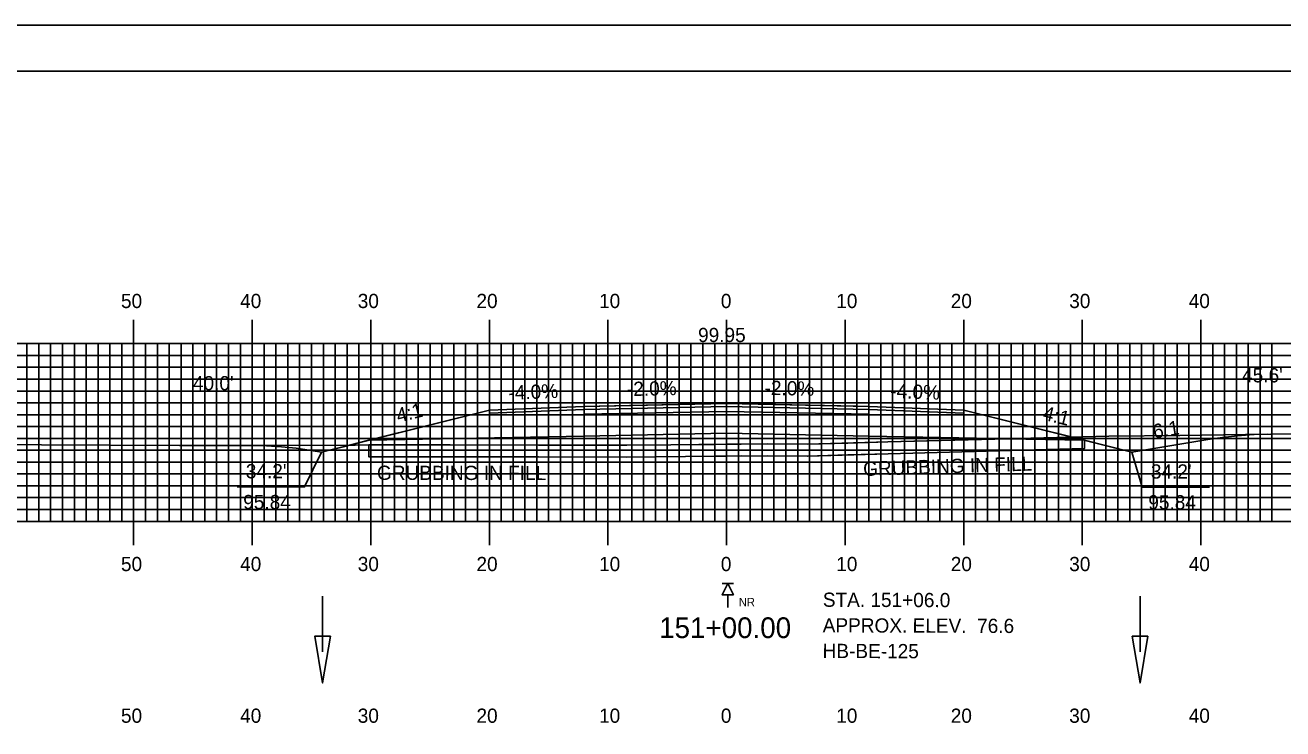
# Model space of a CAD drawing. Extents: x 1778319 to 1778662, y 442591 to 442811.
# Drawn here: x 1778425.2 to 1778531.2, y 442751.2 to 442810.5 of the extents above; entities that cross this region are included whole.
import ezdxf

# ---------------------------------------------------------------- set-up
doc = ezdxf.new("R2010")
doc.units = 0
for name, color, linetype in [('ANNOTATION', 7, 'Continuous'), ('BORDER', 7, 'Continuous'), ('BORING - NO REFUSAL', 7, 'Continuous'), ('D_Drainage_Ditch_Line', 7, 'Continuous'), ('D_Roadway_Centerline', 7, 'Continuous'), ('D_Roadway_Centerline_Text', 7, 'Continuous'), ('D_Roadway_Edge_Shoulder', 7, 'Continuous'), ('D_Roadway_Edge_TW', 7, 'Continuous'), ('D_Roadway_Pavement', 7, 'Continuous'), ('D_Roadway_SlopeLines', 7, 'Continuous'), ('D_Roadway_SubGrade', 7, 'Continuous'), ('D_Text_Standard', 7, 'Continuous'), ('GRUBBING IN FILL', 7, 'Continuous'), ('H_V ANNOTATION', 7, 'Continuous'), ('MAJOR', 7, 'Continuous'), ('MINOR', 7, 'Continuous'), ('PLOT BOUNDARY', 7, 'Continuous'), ('S_Roadway_Centerline', 7, 'Continuous')]:
    doc.layers.add(name, color=color, linetype=linetype)

msp = doc.modelspace()

# ---------------------------------------------------------------- linework, layer by layer
at = {"layer": 'ANNOTATION'}
for points in [[(1778443.02, 442771.57), (1778448.71, 442771.57), (1778450.13, 442774.51)], [(1778525.04, 442771.56), (1778519.35, 442771.56), (1778518.48, 442774.51)]]:
    msp.add_lwpolyline(points, dxfattribs=at)
at = {"layer": 'BORDER'}
msp.add_lwpolyline([(1778334.7, 442596.67), (1778654.7, 442596.67), (1778654.7, 442806.67), (1778334.7, 442806.67)], close=True, dxfattribs=at)
at = {"layer": 'BORING - NO REFUSAL'}
for p, q in [((1778484.88, 442763.43), (1778483.92, 442763.43)), ((1778484.4, 442762.47), (1778484.4, 442761.41))]:
    msp.add_line(p, q, dxfattribs=at)
msp.add_lwpolyline([(1778484.4, 442763.43), (1778484.88, 442762.47), (1778483.92, 442762.47)], close=True, dxfattribs=at)
at = {"layer": 'D_Drainage_Ditch_Line'}
for p, q in [((1778450.24, 442757.66), (1778450.24, 442762.36)), ((1778519.17, 442757.66), (1778519.17, 442762.36))]:
    msp.add_line(p, q, dxfattribs=at)
for points in [[(1778450.9, 442758.97), (1778449.58, 442758.97), (1778450.24, 442755.04)], [(1778519.82, 442758.97), (1778518.51, 442758.97), (1778519.17, 442755.04)]]:
    msp.add_lwpolyline(points, close=True, dxfattribs=at)
at = {"layer": 'D_Roadway_Centerline'}
msp.add_lwpolyline([(1778444.26, 442775.06), (1778445.51, 442775.04), (1778446.76, 442774.97), (1778448.01, 442774.84), (1778449.26, 442774.65), (1778449.96, 442774.54), (1778450.13, 442774.51), (1778451.86, 442774.94), (1778454.13, 442775.51), (1778464.3, 442778.05), (1778472.3, 442778.37), (1778476.13, 442778.45), (1778484.3, 442778.61), (1778495.33, 442778.39), (1778496.3, 442778.37), (1778504.3, 442778.05), (1778514.48, 442775.51), (1778518.48, 442774.51), (1778524.89, 442775.58), (1778526.14, 442775.76), (1778527.39, 442775.9), (1778528.4, 442775.97), (1778528.64, 442775.99), (1778528.81, 442775.99), (1778529.89, 442776.03)], dxfattribs=at)
at = {"layer": 'D_Roadway_Edge_Shoulder'}
for points in [[(1778472.3, 442778.37), (1778464.3, 442778.05), (1778464.3, 442777.8), (1778472.3, 442778.12)], [(1778496.3, 442778.37), (1778504.3, 442778.05), (1778504.3, 442777.8), (1778496.3, 442778.12)]]:
    msp.add_lwpolyline(points, close=True, dxfattribs=at)
at = {"layer": 'D_Roadway_Edge_TW'}
msp.add_lwpolyline([(1778472.3, 442778.12), (1778472.3, 442778.37), (1778484.3, 442778.61), (1778496.3, 442778.37), (1778496.3, 442778.12), (1778484.3, 442778.36)], close=True, dxfattribs=at)
at = {"layer": 'D_Roadway_Pavement'}
msp.add_lwpolyline([(1778472.3, 442777.71), (1778472.3, 442778.12), (1778484.3, 442778.36), (1778496.3, 442778.12), (1778496.3, 442777.71), (1778484.3, 442777.95)], close=True, dxfattribs=at)
at = {"layer": 'D_Roadway_SlopeLines'}
for points in [[(1778464.3, 442778.05), (1778450.13, 442774.51)], [(1778504.3, 442778.05), (1778518.48, 442774.51)], [(1778518.48, 442774.51), (1778524.89, 442775.58), (1778526.14, 442775.76), (1778527.39, 442775.9), (1778528.64, 442775.99), (1778529.89, 442776.03)], [(1778450.13, 442774.51), (1778449.26, 442774.65), (1778448.01, 442774.84), (1778446.76, 442774.97), (1778445.51, 442775.04), (1778444.26, 442775.06)]]:
    msp.add_lwpolyline(points, dxfattribs=at)
at = {"layer": 'D_Roadway_SubGrade'}
msp.add_lwpolyline([(1778472.3, 442775.87), (1778454.13, 442775.51), (1778464.3, 442778.05), (1778464.3, 442777.8), (1778472.3, 442778.12), (1778484.3, 442778.36), (1778496.3, 442778.12), (1778504.3, 442777.8), (1778504.3, 442778.05), (1778514.48, 442775.51), (1778496.3, 442775.87), (1778484.3, 442776.11)], close=True, dxfattribs=at)
at = {"layer": 'GRUBBING IN FILL'}
for p, q in [((1778454.13, 442775.12), (1778454.13, 442774.12)), ((1778454.13, 442775.12), (1778454.13, 442774.12)), ((1778514.48, 442775.51), (1778514.48, 442774.81)), ((1778514.48, 442775.51), (1778514.48, 442774.81))]:
    msp.add_line(p, q, dxfattribs=at)
for points in [[(1778454.13, 442775.12), (1778454.13, 442774.12), (1778460.99, 442774.12), (1778468.44, 442774.11), (1778475.9, 442774.1), (1778483.31, 442774.17), (1778484.3, 442774.18), (1778484.3, 442775.18), (1778479.6, 442775.13), (1778475.89, 442775.1), (1778468.44, 442775.11), (1778460.99, 442775.12)], [(1778454.13, 442775.12), (1778454.13, 442774.12), (1778460.99, 442774.12), (1778468.44, 442774.11), (1778475.9, 442774.1), (1778483.31, 442774.17), (1778484.3, 442774.18), (1778484.3, 442775.18), (1778479.6, 442775.13), (1778475.89, 442775.1), (1778468.44, 442775.11), (1778460.99, 442775.12)], [(1778484.3, 442775.18), (1778487.76, 442775.21), (1778491.14, 442775.18), (1778494.52, 442775.28), (1778497.89, 442775.38), (1778506.93, 442775.62), (1778507.87, 442775.64), (1778514.48, 442775.51), (1778514.48, 442774.81), (1778506.2, 442774.6), (1778497.92, 442774.38), (1778494.54, 442774.28), (1778491.12, 442774.18), (1778485.54, 442774.19), (1778484.3, 442774.18)], [(1778484.3, 442775.18), (1778487.76, 442775.21), (1778491.14, 442775.18), (1778494.52, 442775.28), (1778497.89, 442775.38), (1778506.93, 442775.62), (1778507.87, 442775.64), (1778514.48, 442775.51), (1778514.48, 442774.81), (1778506.2, 442774.6), (1778497.92, 442774.38), (1778494.54, 442774.28), (1778491.12, 442774.18), (1778485.54, 442774.19), (1778484.3, 442774.18)]]:
    msp.add_lwpolyline(points, close=True, dxfattribs=at)
msp.add_lwpolyline([(1778454.13, 442774.12), (1778460.99, 442774.12), (1778475.9, 442774.1), (1778483.31, 442774.17), (1778487.76, 442774.21), (1778491.15, 442774.18), (1778497.92, 442774.38), (1778514.48, 442774.81)], dxfattribs=at)
msp.add_lwpolyline([(1778454.13, 442774.12), (1778460.99, 442774.12), (1778475.9, 442774.1), (1778483.31, 442774.17), (1778487.76, 442774.21), (1778491.15, 442774.18), (1778497.92, 442774.38), (1778514.48, 442774.81)], dxfattribs=at)
at = {"layer": 'MAJOR'}
for p, q in [((1778434.3, 442785.67), (1778434.3, 442783.67)), ((1778444.3, 442785.67), (1778444.3, 442783.67)), ((1778454.3, 442785.67), (1778454.3, 442783.67)), ((1778464.3, 442785.67), (1778464.3, 442783.67)), ((1778474.3, 442785.67), (1778474.3, 442783.67)), ((1778484.3, 442785.67), (1778484.3, 442783.67)), ((1778494.3, 442785.67), (1778494.3, 442783.67)), ((1778504.3, 442785.67), (1778504.3, 442783.67)), ((1778514.3, 442785.67), (1778514.3, 442783.67)), ((1778524.3, 442785.67), (1778524.3, 442783.67)), ((1778344.3, 442783.67), (1778624.3, 442783.67)), ((1778344.3, 442783.67), (1778624.3, 442783.67)), ((1778434.3, 442768.67), (1778434.3, 442783.67)), ((1778444.3, 442768.67), (1778444.3, 442783.67)), ((1778454.3, 442768.67), (1778454.3, 442783.67)), ((1778464.3, 442768.67), (1778464.3, 442783.67)), ((1778474.3, 442768.67), (1778474.3, 442783.67)), ((1778484.3, 442768.67), (1778484.3, 442783.67)), ((1778494.3, 442768.67), (1778494.3, 442783.67)), ((1778504.3, 442768.67), (1778504.3, 442783.67)), ((1778514.3, 442768.67), (1778514.3, 442783.67)), ((1778524.3, 442768.67), (1778524.3, 442783.67)), ((1778344.3, 442778.67), (1778624.3, 442778.67)), ((1778344.3, 442773.67), (1778624.3, 442773.67)), ((1778344.3, 442768.67), (1778624.3, 442768.67)), ((1778344.3, 442768.67), (1778624.3, 442768.67)), ((1778434.3, 442766.66), (1778434.3, 442768.67)), ((1778444.3, 442766.66), (1778444.3, 442768.67)), ((1778454.3, 442766.66), (1778454.3, 442768.67)), ((1778464.3, 442766.66), (1778464.3, 442768.67)), ((1778474.3, 442766.66), (1778474.3, 442768.67)), ((1778484.3, 442766.66), (1778484.3, 442768.67)), ((1778494.3, 442766.66), (1778494.3, 442768.67)), ((1778504.3, 442766.66), (1778504.3, 442768.67)), ((1778514.3, 442766.66), (1778514.3, 442768.67)), ((1778524.3, 442766.66), (1778524.3, 442768.67))]:
    msp.add_line(p, q, dxfattribs=at)
at = {"layer": 'MINOR'}
for p, q in [((1778425.3, 442768.67), (1778425.3, 442783.67)), ((1778426.3, 442768.67), (1778426.3, 442783.67)), ((1778427.3, 442768.67), (1778427.3, 442783.67)), ((1778428.3, 442768.67), (1778428.3, 442783.67)), ((1778429.3, 442768.67), (1778429.3, 442783.67)), ((1778430.3, 442768.67), (1778430.3, 442783.67)), ((1778431.3, 442768.67), (1778431.3, 442783.67)), ((1778432.3, 442768.67), (1778432.3, 442783.67)), ((1778433.3, 442768.67), (1778433.3, 442783.67)), ((1778435.3, 442768.67), (1778435.3, 442783.67)), ((1778436.3, 442768.67), (1778436.3, 442783.67)), ((1778437.3, 442768.67), (1778437.3, 442783.67)), ((1778438.3, 442768.67), (1778438.3, 442783.67)), ((1778439.3, 442768.67), (1778439.3, 442783.67)), ((1778440.3, 442768.67), (1778440.3, 442783.67)), ((1778441.3, 442768.67), (1778441.3, 442783.67)), ((1778442.3, 442768.67), (1778442.3, 442783.67)), ((1778443.3, 442768.67), (1778443.3, 442783.67)), ((1778445.3, 442768.67), (1778445.3, 442783.67)), ((1778446.3, 442768.67), (1778446.3, 442783.67)), ((1778447.3, 442768.67), (1778447.3, 442783.67)), ((1778448.3, 442768.67), (1778448.3, 442783.67)), ((1778449.3, 442768.67), (1778449.3, 442783.67)), ((1778450.3, 442768.67), (1778450.3, 442783.67)), ((1778451.3, 442768.67), (1778451.3, 442783.67)), ((1778452.3, 442768.67), (1778452.3, 442783.67)), ((1778453.3, 442768.67), (1778453.3, 442783.67)), ((1778455.3, 442768.67), (1778455.3, 442783.67)), ((1778456.3, 442768.67), (1778456.3, 442783.67)), ((1778457.3, 442768.67), (1778457.3, 442783.67)), ((1778458.3, 442768.67), (1778458.3, 442783.67)), ((1778459.3, 442768.67), (1778459.3, 442783.67)), ((1778460.3, 442768.67), (1778460.3, 442783.67)), ((1778461.3, 442768.67), (1778461.3, 442783.67)), ((1778462.3, 442768.67), (1778462.3, 442783.67)), ((1778463.3, 442768.67), (1778463.3, 442783.67)), ((1778465.3, 442768.67), (1778465.3, 442783.67)), ((1778466.3, 442768.67), (1778466.3, 442783.67)), ((1778467.3, 442768.67), (1778467.3, 442783.67)), ((1778468.3, 442768.67), (1778468.3, 442783.67)), ((1778469.3, 442768.67), (1778469.3, 442783.67)), ((1778470.3, 442768.67), (1778470.3, 442783.67)), ((1778471.3, 442768.67), (1778471.3, 442783.67)), ((1778472.3, 442768.67), (1778472.3, 442783.67)), ((1778473.3, 442768.67), (1778473.3, 442783.67)), ((1778475.3, 442768.67), (1778475.3, 442783.67)), ((1778476.3, 442768.67), (1778476.3, 442783.67)), ((1778477.3, 442768.67), (1778477.3, 442783.67)), ((1778478.3, 442768.67), (1778478.3, 442783.67)), ((1778479.3, 442768.67), (1778479.3, 442783.67)), ((1778480.3, 442768.67), (1778480.3, 442783.67)), ((1778481.3, 442768.67), (1778481.3, 442783.67)), ((1778482.3, 442768.67), (1778482.3, 442783.67)), ((1778483.3, 442768.67), (1778483.3, 442783.67)), ((1778485.3, 442768.67), (1778485.3, 442783.67)), ((1778486.3, 442768.67), (1778486.3, 442783.67)), ((1778487.3, 442768.67), (1778487.3, 442783.67)), ((1778488.3, 442768.67), (1778488.3, 442783.67)), ((1778489.3, 442768.67), (1778489.3, 442783.67)), ((1778490.3, 442768.67), (1778490.3, 442783.67)), ((1778491.3, 442768.67), (1778491.3, 442783.67)), ((1778492.3, 442768.67), (1778492.3, 442783.67)), ((1778493.3, 442768.67), (1778493.3, 442783.67)), ((1778495.3, 442768.67), (1778495.3, 442783.67)), ((1778496.3, 442768.67), (1778496.3, 442783.67)), ((1778497.3, 442768.67), (1778497.3, 442783.67)), ((1778498.3, 442768.67), (1778498.3, 442783.67)), ((1778499.3, 442768.67), (1778499.3, 442783.67)), ((1778500.3, 442768.67), (1778500.3, 442783.67)), ((1778501.3, 442768.67), (1778501.3, 442783.67)), ((1778502.3, 442768.67), (1778502.3, 442783.67)), ((1778503.3, 442768.67), (1778503.3, 442783.67)), ((1778505.3, 442768.67), (1778505.3, 442783.67)), ((1778506.3, 442768.67), (1778506.3, 442783.67)), ((1778507.3, 442768.67), (1778507.3, 442783.67)), ((1778508.3, 442768.67), (1778508.3, 442783.67)), ((1778509.3, 442768.67), (1778509.3, 442783.67)), ((1778510.3, 442768.67), (1778510.3, 442783.67)), ((1778511.3, 442768.67), (1778511.3, 442783.67)), ((1778512.3, 442768.67), (1778512.3, 442783.67)), ((1778513.3, 442768.67), (1778513.3, 442783.67)), ((1778515.3, 442768.67), (1778515.3, 442783.67)), ((1778516.3, 442768.67), (1778516.3, 442783.67)), ((1778517.3, 442768.67), (1778517.3, 442783.67)), ((1778518.3, 442768.67), (1778518.3, 442783.67)), ((1778519.3, 442768.67), (1778519.3, 442783.67)), ((1778520.3, 442768.67), (1778520.3, 442783.67)), ((1778521.3, 442768.67), (1778521.3, 442783.67)), ((1778522.3, 442768.67), (1778522.3, 442783.67)), ((1778523.3, 442768.67), (1778523.3, 442783.67)), ((1778525.3, 442768.67), (1778525.3, 442783.67)), ((1778526.3, 442768.67), (1778526.3, 442783.67)), ((1778527.3, 442768.67), (1778527.3, 442783.67)), ((1778528.3, 442768.67), (1778528.3, 442783.67)), ((1778529.3, 442768.67), (1778529.3, 442783.67)), ((1778530.3, 442768.67), (1778530.3, 442783.67)), ((1778344.3, 442782.67), (1778624.3, 442782.67)), ((1778344.3, 442781.67), (1778624.3, 442781.67)), ((1778344.3, 442780.67), (1778624.3, 442780.67)), ((1778344.3, 442779.67), (1778624.3, 442779.67)), ((1778344.3, 442777.67), (1778624.3, 442777.67)), ((1778344.3, 442776.67), (1778624.3, 442776.67)), ((1778344.3, 442775.67), (1778624.3, 442775.67)), ((1778344.3, 442774.67), (1778624.3, 442774.67)), ((1778344.3, 442772.67), (1778624.3, 442772.67)), ((1778344.3, 442771.67), (1778624.3, 442771.67)), ((1778344.3, 442770.67), (1778624.3, 442770.67)), ((1778344.3, 442769.67), (1778624.3, 442769.67))]:
    msp.add_line(p, q, dxfattribs=at)
at = {"layer": 'PLOT BOUNDARY'}
msp.add_lwpolyline([(1778318.52, 442590.55), (1778658.52, 442590.55), (1778658.52, 442810.55), (1778318.52, 442810.55)], close=True, dxfattribs=at)
at = {"layer": 'S_Roadway_Centerline'}
msp.add_lwpolyline([(1778344.3, 442773.75), (1778347.05, 442773.91), (1778348.74, 442773.96), (1778368.68, 442774.24), (1778374.49, 442774.36), (1778392.65, 442775.09), (1778395.99, 442775.16), (1778406.46, 442774.91), (1778414.67, 442775.1), (1778417.42, 442775.17), (1778420.68, 442775.16), (1778438.17, 442775.07), (1778445.29, 442775.06), (1778452.97, 442775.11), (1778460.99, 442775.12), (1778475.89, 442775.1), (1778483.3, 442775.17), (1778487.76, 442775.21), (1778491.14, 442775.18), (1778497.89, 442775.38), (1778516.54, 442775.87), (1778522.54, 442775.91), (1778528.07, 442776.01), (1778538.8, 442776.13)], dxfattribs=at)

# ---------------------------------------------------------------- texts
at = {"layer": 'ANNOTATION'}
for s, rotation, p in [('-4.0%', 2.2905, (1778465.93, 442778.92)), ('-2.0%', 1.1458, (1778475.91, 442779.24)), ('-2.0%', 358.8542, (1778487.5, 442779.35)), ('-4.0%', 357.7095, (1778498.09, 442779.1)), ('4:1', 14.0347, (1778456.62, 442776.99)), ('4:1', 345.966, (1778510.9, 442777.27)), ('6:1', 9.4626, (1778520.36, 442775.65))]:
    msp.add_text(s, height=1.2, rotation=rotation, dxfattribs=at).set_placement(p)
for s, p in [("34.2'", (1778443.76, 442772.3)), ("34.2'", (1778520.09, 442772.28)), ('95.84', (1778443.54, 442769.7)), ('95.84', (1778519.87, 442769.68))]:
    msp.add_text(s, height=1.2, dxfattribs=at).set_placement(p)
at = {"layer": 'BORING - NO REFUSAL'}
msp.add_text('NR', height=0.7, dxfattribs=at).set_placement((1778485.34, 442761.51))
for s, p in [('STA. 151+06.0', (1778492.42, 442761.46)), ('APPROX. ELEV.  76.6', (1778492.41, 442759.3)), ('HB-BE-125', (1778492.4, 442757.14))]:
    msp.add_text(s, height=1.2, rotation=359.8142, dxfattribs=at).set_placement(p)
at = {"layer": 'D_Roadway_Centerline'}
for s, p in [('C', (1778484.3, 442778.61)), ('L', (1778484.3, 442778.6))]:
    msp.add_text(s, height=0.0146, dxfattribs=at).set_placement(p)
at = {"layer": 'D_Roadway_Centerline_Text'}
msp.add_text('99.95', height=1.2, dxfattribs=at).set_placement((1778481.9, 442783.8))
at = {"layer": 'D_Text_Standard'}
for s, p in [("45.6'", (1778527.78, 442780.4)), ("40.0'", (1778439.3, 442779.73))]:
    msp.add_text(s, height=1.2, dxfattribs=at).set_placement(p)
at = {"layer": 'GRUBBING IN FILL'}
for rotation, p in [(1.8268, (1778495.84, 442772.5)), (359.9351, (1778454.82, 442772.17))]:
    msp.add_text('GRUBBING IN FILL', height=1.2, rotation=rotation, dxfattribs=at).set_placement(p)
at = {"layer": 'H_V ANNOTATION'}
for s, height, p in [('50', 1.2, (1778433.23, 442786.67)), ('40', 1.2, (1778443.28, 442786.67)), ('30', 1.2, (1778453.2, 442786.67)), ('20', 1.2, (1778463.21, 442786.67)), ('10', 1.2, (1778473.55, 442786.67)), ('0', 1.2, (1778483.82, 442786.67)), ('10', 1.2, (1778493.55, 442786.67)), ('20', 1.2, (1778503.21, 442786.67)), ('30', 1.2, (1778513.2, 442786.67)), ('40', 1.2, (1778523.28, 442786.67)), ('50', 1.2, (1778433.23, 442764.47)), ('40', 1.2, (1778443.28, 442764.47)), ('30', 1.2, (1778453.2, 442764.47)), ('20', 1.2, (1778463.21, 442764.47)), ('10', 1.2, (1778473.55, 442764.47)), ('0', 1.2, (1778483.82, 442764.47)), ('10', 1.2, (1778493.55, 442764.47)), ('20', 1.2, (1778503.21, 442764.47)), ('30', 1.2, (1778513.2, 442764.47)), ('40', 1.2, (1778523.28, 442764.47)), ('151+00.00', 1.75, (1778478.62, 442758.82)), ('50', 1.2, (1778433.23, 442751.67)), ('40', 1.2, (1778443.28, 442751.67)), ('30', 1.2, (1778453.2, 442751.67)), ('20', 1.2, (1778463.21, 442751.67)), ('10', 1.2, (1778473.55, 442751.67)), ('0', 1.2, (1778483.82, 442751.67)), ('10', 1.2, (1778493.55, 442751.67)), ('20', 1.2, (1778503.21, 442751.67)), ('30', 1.2, (1778513.2, 442751.67)), ('40', 1.2, (1778523.28, 442751.67))]:
    msp.add_text(s, height=height, dxfattribs=at).set_placement(p)

doc.saveas('drawing.dxf')
